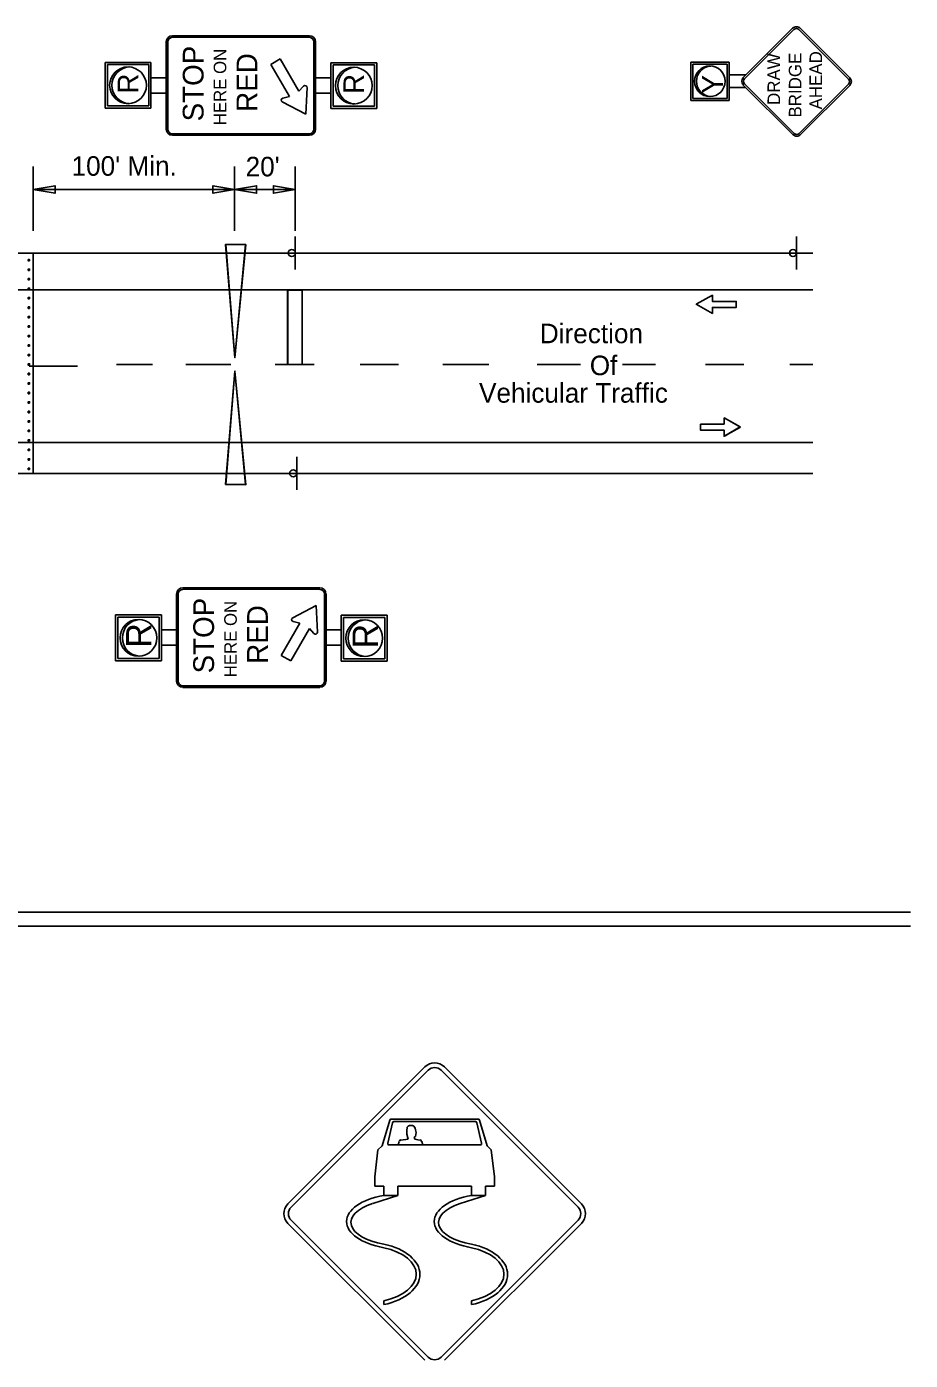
# Model space of a CAD drawing. Extents: x 15 to 764, y 7 to 487.
# Drawn here: x 605.9 to 764.1, y 233.7 to 472.6 of the extents above; entities that cross this region are included whole.
import ezdxf

# ---------------------------------------------------------------- set-up
doc = ezdxf.new("R2010")
doc.units = 0
for name, color, linetype in [('Default', 7, 'Continuous'), ('Dimension', 7, 'Continuous'), ('TextStructures', 7, 'Continuous')]:
    doc.layers.add(name, color=color, linetype=linetype)

msp = doc.modelspace()

# ---------------------------------------------------------------- linework, layer by layer
at = {"layer": 'Default'}
for p, q in [((656.48, 470.93), (631.96, 470.93)), ((656.48, 470.65), (631.96, 470.65)), ((743, 472.27), (734.18, 463.45)), ((743.23, 472.04), (734.41, 463.23)), ((753.01, 463.16), (744.13, 472.04)), ((753.24, 463.38), (744.36, 472.27)), ((630.84, 469.81), (630.84, 454.21)), ((631.12, 469.81), (631.12, 454.21)), ((657.31, 454.21), (657.31, 469.81)), ((657.59, 454.21), (657.59, 469.81)), ((628.13, 466.16), (619.91, 466.16)), ((619.91, 466.16), (619.91, 457.94)), ((628.13, 457.94), (628.13, 466.16)), ((651.26, 466.77), (649.58, 465.8)), ((654.6, 461), (651.26, 466.77)), ((668.55, 466.1), (660.33, 466.1)), ((660.33, 466.1), (660.33, 457.88)), ((668.55, 457.88), (668.55, 466.1)), ((731.62, 466.19), (724.76, 466.19)), ((724.76, 466.19), (724.76, 459.34)), ((731.27, 465.85), (725.11, 465.85)), ((725.11, 465.85), (725.11, 459.69)), ((731.27, 459.69), (731.27, 465.85)), ((731.62, 459.34), (731.62, 466.19)), ((627.72, 465.75), (620.32, 465.75)), ((620.32, 465.75), (620.32, 458.35)), ((627.72, 458.35), (627.72, 465.75)), ((649.58, 465.8), (652.91, 460.02)), ((668.14, 465.69), (660.74, 465.69)), ((660.74, 465.69), (660.74, 458.29)), ((668.14, 458.29), (668.14, 465.69)), ((731.64, 463.9), (734.63, 463.9)), ((628.12, 463.37), (630.84, 463.37)), ((655.44, 461.89), (654.6, 461)), ((655.85, 456.87), (656.07, 461.63)), ((657.59, 463.37), (660.31, 463.37)), ((731.64, 461.64), (734.64, 461.64)), ((743.06, 453.21), (734.18, 462.1)), ((743.29, 453.44), (734.41, 462.33)), ((740.2, 461.17), (740.2, 461.18)), ((753.01, 462.26), (744.19, 453.44)), ((753.24, 462.03), (744.42, 453.21)), ((628.12, 460.65), (630.84, 460.65)), ((651.63, 459.06), (655.85, 456.87)), ((652.91, 460.02), (651.72, 459.74)), ((657.59, 460.65), (660.31, 460.65)), ((724.76, 459.34), (731.62, 459.34)), ((725.11, 459.69), (731.27, 459.69)), ((619.91, 457.94), (628.13, 457.94)), ((620.32, 458.35), (627.72, 458.35)), ((660.33, 457.88), (668.55, 457.88)), ((660.74, 458.29), (668.14, 458.29)), ((631.96, 453.37), (656.48, 453.37)), ((631.96, 453.09), (656.48, 453.09)), ((607.05, 436.01), (607.05, 447.48)), ((643.11, 436.01), (643.11, 447.48)), ((653.97, 436.01), (653.97, 447.48)), ((607.05, 443.39), (643.11, 443.39)), ((643.11, 443.39), (653.97, 443.39)), ((653.97, 429.04), (653.97, 434.99)), ((743.71, 429.04), (743.71, 434.99)), ((645.08, 433.54), (641.47, 433.54)), ((641.47, 433.54), (643.15, 413.21)), ((645.08, 433.54), (641.52, 433.54)), ((643.15, 413.21), (645.08, 433.54)), ((643.16, 413.27), (645.08, 433.54)), ((401.85, 431.97), (746.65, 431.97)), ((607.05, 431.97), (539.34, 431.97)), ((607.05, 392.5), (607.05, 431.97)), ((607.05, 431.97), (641.6, 431.97)), ((401.85, 425.41), (746.65, 425.41)), ((728.65, 424.44), (725.74, 422.82)), ((728.65, 423.35), (728.65, 424.44)), ((728.65, 423.35), (728.65, 424.01)), ((732.91, 423.35), (728.65, 423.35)), ((731.99, 423.35), (728.65, 423.35)), ((732.91, 422.26), (732.91, 423.35)), ((725.74, 422.82), (728.64, 421.17)), ((728.64, 421.17), (728.64, 422.26)), ((728.64, 422.26), (732.91, 422.26)), ((728.64, 421.17), (728.64, 422.26)), ((728.64, 422.26), (728.66, 422.26)), ((728.64, 421.18), (728.64, 421.17)), ((606.33, 411.74), (614.98, 411.74)), ((621.96, 412.04), (628.41, 412.04)), ((634.39, 412.04), (642.45, 412.04)), ((650.35, 412.04), (657.35, 412.04)), ((652.62, 412.04), (655.21, 412.04)), ((665.59, 412.04), (672.45, 412.04)), ((680.37, 412.04), (688.63, 412.04)), ((697.28, 412.04), (705, 412.04)), ((712.54, 412.04), (718.47, 412.04)), ((727.39, 412.04), (734.27, 412.04)), ((742.51, 412.04), (746.65, 412.04)), ((641.47, 390.53), (643.15, 410.86)), ((643.15, 410.86), (645.08, 390.53)), ((645.08, 390.53), (643.15, 410.86)), ((730.74, 401.38), (726.49, 401.37)), ((730.74, 401.38), (726.49, 401.37)), ((726.49, 401.37), (726.49, 400.28)), ((730.75, 402.47), (730.74, 401.38)), ((730.75, 402.47), (730.74, 401.38)), ((733.65, 400.82), (730.75, 402.47)), ((733.61, 400.85), (730.75, 402.47)), ((726.49, 400.28), (730.74, 400.28)), ((730.74, 399.2), (733.65, 400.82)), ((730.74, 400.28), (730.74, 399.2)), ((730.74, 399.2), (730.9, 399.29)), ((401.85, 398.09), (746.65, 398.09)), ((654.24, 389.57), (654.24, 395.51)), ((401.85, 392.5), (746.65, 392.5)), ((539.34, 392.5), (607.05, 392.5)), ((645.08, 390.53), (641.47, 390.53)), ((641.51, 390.53), (645.08, 390.53)), ((632.72, 370.93), (632.72, 355.33)), ((633, 370.93), (633, 355.33)), ((658.35, 372.05), (633.83, 372.05)), ((658.35, 371.77), (633.83, 371.77)), ((659.19, 355.33), (659.19, 370.93)), ((659.47, 355.33), (659.47, 370.93)), ((653.51, 366.68), (657.73, 368.87)), ((657.73, 368.87), (657.95, 364.11)), ((629.99, 367.18), (621.77, 367.18)), ((621.77, 367.18), (621.77, 358.96)), ((629.58, 366.77), (622.18, 366.77)), ((622.18, 366.77), (622.18, 359.37)), ((629.58, 359.37), (629.58, 366.77)), ((629.99, 358.96), (629.99, 367.18)), ((651.45, 359.94), (654.79, 365.72)), ((654.79, 365.72), (653.59, 366)), ((670.42, 367.13), (662.2, 367.13)), ((662.2, 367.13), (662.2, 358.91)), ((670.01, 366.72), (662.61, 366.72)), ((662.61, 366.72), (662.61, 359.32)), ((670.01, 359.32), (670.01, 366.72)), ((670.42, 358.91), (670.42, 367.13)), ((630, 364.49), (632.72, 364.49)), ((656.48, 364.74), (653.14, 358.97)), ((657.31, 363.85), (656.48, 364.74)), ((659.47, 364.49), (662.19, 364.49)), ((630, 361.77), (632.72, 361.77)), ((659.47, 361.77), (662.19, 361.77)), ((621.77, 358.96), (629.99, 358.96)), ((622.18, 359.37), (629.58, 359.37)), ((653.14, 358.97), (651.45, 359.94)), ((662.2, 358.91), (670.42, 358.91)), ((662.61, 359.32), (670.01, 359.32)), ((633.83, 354.49), (658.35, 354.49)), ((633.83, 354.21), (658.35, 354.21)), ((677.16, 286.21), (652.64, 261.69)), ((677.75, 285.63), (653.23, 261.11)), ((704.6, 261.11), (680.08, 285.63)), ((705.19, 261.69), (680.67, 286.21)), ((669.5, 272.09), (670.9, 276.71)), ((671.38, 276.23), (670.51, 272.55)), ((671.14, 276.89), (686.69, 276.89)), ((686.2, 276.42), (671.63, 276.42)), ((673.92, 274.8), (674, 275.43)), ((673.92, 274.16), (673.92, 274.8)), ((674, 275.43), (674.16, 275.59)), ((675.19, 275.59), (675.43, 275.27)), ((675.43, 275.27), (675.5, 274.95)), ((675.5, 274.95), (675.58, 274.48)), ((687.32, 272.55), (686.44, 276.23)), ((686.93, 276.71), (688.33, 272.09)), ((672.41, 272.26), (672.57, 272.89)), ((672.89, 273.13), (674.16, 273.29)), ((674.16, 273.29), (673.92, 274.16)), ((675.35, 273.77), (675.27, 273.61)), ((675.27, 273.61), (675.35, 273.29)), ((675.5, 273.77), (675.35, 273.77)), ((675.35, 273.29), (676.22, 273.13)), ((675.58, 274.48), (675.5, 273.77)), ((676.61, 272.89), (676.77, 272.26)), ((668.18, 266.51), (668.77, 271.36)), ((668.77, 271.36), (669.5, 272.09)), ((670.75, 272.24), (687.08, 272.24)), ((676.78, 272.24), (672.45, 272.24)), ((688.33, 272.09), (689.06, 271.36)), ((689.06, 271.36), (689.65, 266.51)), ((668.18, 264.86), (668.18, 266.51)), ((689.65, 266.51), (689.65, 264.86)), ((672.31, 263.21), (667.82, 261.73)), ((669.83, 264.86), (668.18, 264.86)), ((669.83, 263.21), (669.83, 264.86)), ((669.83, 263.21), (672.31, 263.21)), ((672.31, 263.21), (669.83, 263.21)), ((685.52, 264.86), (672.31, 264.86)), ((672.31, 264.86), (672.31, 263.21)), ((688, 263.21), (683.5, 261.73)), ((685.52, 263.21), (685.52, 264.86)), ((685.52, 263.21), (688, 263.21)), ((688, 263.21), (685.52, 263.21)), ((689.65, 264.86), (688, 264.86)), ((688, 264.86), (688, 263.21)), ((652.64, 258.19), (677.16, 233.67)), ((653.23, 258.77), (677.75, 234.25)), ((680.08, 234.25), (704.6, 258.77)), ((680.67, 233.67), (705.19, 258.19)), ((669.83, 243.65), (669.83, 244.35)), ((685.52, 243.65), (685.52, 244.35))]:
    msp.add_line(p, q, dxfattribs=at)
for points in [[(645.11, 433.56), (641.52, 433.56), (643.16, 413.27)], [(652.59, 425.41), (652.59, 412.04), (655.22, 412.04), (655.22, 425.41)], [(655.18, 425.41), (652.62, 425.41), (652.62, 412.03), (655.21, 412.03)], [(728.64, 424.44), (725.75, 422.82), (728.64, 421.18), (728.66, 422.26), (732.91, 422.27), (732.9, 423.35), (728.66, 423.35)], [(641.51, 390.53), (645.12, 390.49), (643.15, 410.86)], [(726.49, 401.37), (730.74, 401.39), (730.75, 402.47), (733.61, 400.85), (730.88, 399.28), (730.73, 399.2), (730.73, 400.28), (726.49, 400.29)]]:
    msp.add_lwpolyline(points, close=True, dxfattribs=at)
for points in [[(641.52, 433.54), (643.16, 413.27)], [(606.4, 430.58), (606.4, 430.84), (606.14, 430.84), (606.14, 430.58), (606.4, 430.58)], [(606.4, 430.58), (606.4, 430.84), (606.14, 430.84), (606.14, 430.58), (606.4, 430.58)], [(606.4, 428.89), (606.4, 429.14), (606.14, 429.14), (606.14, 428.89), (606.4, 428.89)], [(606.4, 428.89), (606.4, 429.14), (606.14, 429.14), (606.14, 428.89), (606.4, 428.89)], [(606.4, 427.19), (606.4, 427.44), (606.14, 427.44), (606.14, 427.19), (606.4, 427.19)], [(606.4, 427.19), (606.4, 427.44), (606.14, 427.44), (606.14, 427.19), (606.4, 427.19)], [(606.4, 425.49), (606.4, 425.74), (606.14, 425.74), (606.14, 425.49), (606.4, 425.49)], [(606.4, 425.49), (606.4, 425.74), (606.14, 425.74), (606.14, 425.49), (606.4, 425.49)], [(652.59, 425.38), (655.22, 425.38)], [(655.18, 425.38), (652.62, 425.38)], [(652.62, 425.38), (652.62, 412.04)], [(655.21, 412.04), (655.18, 425.38)], [(606.4, 423.79), (606.4, 424.05), (606.14, 424.05), (606.14, 423.79), (606.4, 423.79)], [(606.4, 423.79), (606.4, 424.05), (606.14, 424.05), (606.14, 423.79), (606.4, 423.79)], [(728.65, 424.01), (728.64, 424.44), (725.75, 422.82), (728.64, 421.18)], [(728.66, 422.26), (732.91, 422.27), (732.9, 423.35), (731.99, 423.35)], [(606.4, 422.09), (606.4, 422.35), (606.14, 422.35), (606.14, 422.09), (606.4, 422.09)], [(606.4, 422.09), (606.4, 422.35), (606.14, 422.35), (606.14, 422.09), (606.4, 422.09)], [(606.4, 420.39), (606.4, 420.65), (606.14, 420.65), (606.14, 420.39), (606.4, 420.39)], [(606.4, 420.39), (606.4, 420.65), (606.14, 420.65), (606.14, 420.39), (606.4, 420.39)], [(606.4, 418.7), (606.4, 418.95), (606.14, 418.95), (606.14, 418.7), (606.4, 418.7)], [(606.4, 418.7), (606.4, 418.95), (606.14, 418.95), (606.14, 418.7), (606.4, 418.7)], [(606.4, 417), (606.4, 417.25), (606.14, 417.25), (606.14, 417), (606.4, 417)], [(606.4, 417), (606.4, 417.25), (606.14, 417.25), (606.14, 417), (606.4, 417)], [(606.4, 415.3), (606.4, 415.55), (606.14, 415.55), (606.14, 415.3), (606.4, 415.3)], [(606.4, 415.3), (606.4, 415.55), (606.14, 415.55), (606.14, 415.3), (606.4, 415.3)], [(606.4, 413.6), (606.4, 413.86), (606.14, 413.85), (606.14, 413.6), (606.4, 413.6)], [(606.4, 413.6), (606.4, 413.86), (606.14, 413.85), (606.14, 413.6), (606.4, 413.6)], [(606.4, 411.9), (606.4, 412.16), (606.14, 412.16), (606.14, 411.9), (606.4, 411.9)], [(606.4, 411.9), (606.4, 412.16), (606.14, 412.16), (606.14, 411.9), (606.4, 411.9)], [(606.4, 410.2), (606.4, 410.46), (606.14, 410.46), (606.14, 410.2), (606.4, 410.2)], [(606.4, 410.2), (606.4, 410.46), (606.14, 410.46), (606.14, 410.2), (606.4, 410.2)], [(606.4, 408.5), (606.4, 408.76), (606.14, 408.76), (606.14, 408.5), (606.4, 408.5)], [(606.4, 408.5), (606.4, 408.76), (606.14, 408.76), (606.14, 408.5), (606.4, 408.5)], [(643.15, 410.86), (641.51, 390.53)], [(606.4, 406.81), (606.4, 407.06), (606.14, 407.06), (606.14, 406.81), (606.4, 406.81)], [(606.4, 406.81), (606.4, 407.06), (606.14, 407.06), (606.14, 406.81), (606.4, 406.81)], [(606.4, 405.11), (606.4, 405.36), (606.14, 405.36), (606.14, 405.11), (606.4, 405.11)], [(606.4, 405.11), (606.4, 405.36), (606.14, 405.36), (606.14, 405.11), (606.4, 405.11)], [(606.4, 403.41), (606.4, 403.66), (606.14, 403.66), (606.14, 403.41), (606.4, 403.41)], [(606.4, 403.41), (606.4, 403.66), (606.14, 403.66), (606.14, 403.41), (606.4, 403.41)], [(606.4, 401.71), (606.4, 401.97), (606.14, 401.97), (606.14, 401.71), (606.4, 401.71)], [(606.4, 401.71), (606.4, 401.97), (606.14, 401.97), (606.14, 401.71), (606.4, 401.71)], [(726.49, 401.37), (726.49, 400.29), (730.73, 400.28)], [(606.4, 400.01), (606.4, 400.27), (606.14, 400.27), (606.14, 400.01), (606.4, 400.01)], [(606.4, 400.01), (606.4, 400.27), (606.14, 400.27), (606.14, 400.01), (606.4, 400.01)], [(730.73, 400.28), (730.73, 399.2)], [(730.9, 399.29), (733.61, 400.85)], [(606.4, 398.31), (606.4, 398.57), (606.14, 398.57), (606.14, 398.31), (606.4, 398.31)], [(606.4, 398.31), (606.4, 398.57), (606.14, 398.57), (606.14, 398.31), (606.4, 398.31)], [(606.4, 396.61), (606.4, 396.87), (606.14, 396.87), (606.14, 396.61), (606.4, 396.61)], [(606.4, 396.61), (606.4, 396.87), (606.14, 396.87), (606.14, 396.61), (606.4, 396.61)], [(606.4, 394.92), (606.4, 395.17), (606.14, 395.17), (606.14, 394.92), (606.4, 394.92)], [(606.4, 394.92), (606.4, 395.17), (606.14, 395.17), (606.14, 394.92), (606.4, 394.92)], [(606.4, 393.22), (606.4, 393.47), (606.14, 393.47), (606.14, 393.22), (606.4, 393.22)], [(606.4, 393.22), (606.4, 393.47), (606.14, 393.47), (606.14, 393.22), (606.4, 393.22)]]:
    msp.add_lwpolyline(points, dxfattribs=at)
for centre, radius in [((624.02, 462.05), 3.29), ((664.44, 461.99), 3.29), ((728.19, 462.77), 2.74), ((653.33, 432.02), 0.637), ((743.07, 432.01), 0.637), ((653.6, 392.54), 0.637), ((625.88, 363.07), 3.29), ((666.31, 363.02), 3.29)]:
    msp.add_circle(centre, radius, dxfattribs=at)
for centre, radius, start, end in [((631.96, 469.81), 1.11, 90, 180), ((631.96, 469.81), 0.836, 90, 180), ((656.48, 469.81), 1.11, 360, 90), ((656.48, 469.81), 0.836, 360, 90), ((743.68, 471.59), 0.958, 44.9848, 134.9852), ((743.68, 471.59), 0.635, 44.9848, 134.9852), ((624.43, 462.05), 3.29, 93.5833, 266.4167), ((664.85, 461.99), 3.29, 93.5833, 266.4167), ((728.53, 462.77), 2.74, 93.5833, 266.4167), ((734.86, 462.78), 0.958, 134.9852, 224.9843), ((655.7, 461.64), 0.366, 357.4033, 136.9437), ((734.86, 462.78), 0.635, 134.9852, 224.9843), ((752.56, 462.71), 0.635, 314.9857, 44.9846), ((752.56, 462.71), 0.958, 314.9857, 44.9846), ((651.8, 459.39), 0.366, 103.0563, 242.5967), ((631.96, 454.21), 1.11, 180, 270), ((631.96, 454.21), 0.836, 180, 270), ((656.48, 454.21), 1.11, 270, 360), ((656.48, 454.21), 0.836, 270, 360), ((743.74, 453.89), 0.958, 224.9847, 314.9857), ((743.74, 453.89), 0.635, 224.9847, 314.9857), ((633.83, 370.93), 1.11, 90, 180), ((633.83, 370.93), 0.836, 90, 180), ((658.35, 370.93), 1.11, 360, 90), ((658.35, 370.93), 0.836, 360, 90), ((626.29, 363.07), 3.29, 93.5833, 266.4167), ((653.67, 366.35), 0.366, 117.4033, 256.9437), ((666.72, 363.02), 3.29, 93.5833, 266.4167), ((657.58, 364.1), 0.366, 223.0563, 2.5967), ((633.83, 355.33), 1.11, 180, 270), ((633.83, 355.33), 0.836, 180, 270), ((658.35, 355.33), 1.11, 270, 360), ((658.35, 355.33), 0.836, 270, 360), ((678.91, 284.46), 2.48, 45, 135), ((678.91, 284.46), 1.65, 45, 135), ((671.14, 276.64), 0.248, 90, 163.133), ((671.63, 276.17), 0.248, 90, 166.6434), ((674.67, 274.65), 1.1, 61.5674, 118.4326), ((686.2, 276.17), 0.248, 13.3566, 90), ((686.69, 276.64), 0.248, 16.8669, 90), ((670.75, 272.49), 0.248, 166.6434, 270), ((672.89, 272.85), 0.303, 96.2729, 166.6932), ((676.21, 272.78), 0.392, 16.03, 82.8338), ((687.08, 272.49), 0.248, 270, 13.3566), ((654.39, 259.94), 2.48, 135, 225), ((654.39, 259.94), 1.65, 135, 225), ((703.43, 259.94), 1.65, 315, 45), ((703.43, 259.94), 2.48, 315, 45), ((678.91, 235.42), 1.65, 225, 315)]:
    msp.add_arc(centre, radius, start, end, dxfattribs=at)
for centre, major_axis, ratio, start_param, end_param in [((673.06, 258.53), (9.91, 0), 0.5, 1.902923, 4.380262), ((688.75, 258.53), (9.91, 0), 0.5, 1.902923, 4.380262), ((673.01, 258.35), (9.08, 0), 0.454545, 2.180257, 4.354407), ((688.7, 258.35), (9.08, 0), 0.454545, 2.180257, 4.354407), ((666.38, 249.06), (9.91, 0), 0.583333, 5.068422, 7.497948), ((666.38, 249.09), (9.25, 0), 0.553572, 5.095121, 7.47125), ((682.07, 249.06), (9.91, 0), 0.583333, 5.068422, 7.497948), ((682.07, 249.09), (9.25, 0), 0.553572, 5.095121, 7.47125)]:
    msp.add_ellipse(centre, major_axis=major_axis, ratio=ratio, start_param=start_param, end_param=end_param, dxfattribs=at)
at = {"layer": 'Dimension'}
for points in [[(607.05, 443.39), (610.96, 442.72), (610.96, 444.05)], [(643.11, 443.39), (639.21, 444.05), (639.21, 442.72)], [(643.11, 443.39), (647.02, 442.72), (647.02, 444.05)], [(653.97, 443.39), (650.06, 444.05), (650.06, 442.72)]]:
    msp.add_lwpolyline(points, close=True, dxfattribs=at)
at = {"layer": 'TextStructures'}
for p, q in [((446.19, 313.96), (764.08, 313.96)), ((446.19, 311.46), (764.08, 311.46))]:
    msp.add_line(p, q, dxfattribs=at)

# ---------------------------------------------------------------- texts
at = {"layer": 'Default'}
for s, height, p in [('STOP', 3.718, (637.54, 455.59)), ('HERE ON', 2.247, (641.61, 454.9)), ('RED', 3.718, (647.17, 457.3)), ('DRAW', 2.265, (740.77, 458.53)), ('BRIDGE', 2.265, (744.59, 456.28)), ('AHEAD', 2.265, (748.29, 457.72)), ('STOP', 3.718, (639.42, 356.71)), ('HERE ON', 2.247, (643.49, 356.02)), ('RED', 3.718, (649.05, 358.43))]:
    msp.add_text(s, height=height, rotation=90, dxfattribs=at).set_placement(p)
at = {"layer": 'TextStructures'}
for s, height, rotation, p in [('R', 3.7, 90, (625.87, 460.57)), ('R', 3.7, 90, (666.29, 460.51)), ('Y', 3.78, 90, (730.55, 460.54)), ("100' Min.", 3.5, 0.0007, (613.91, 445.85)), ("20'", 3.5, 0.0007, (645.07, 445.74)), ('R', 4.54, 90, (628.21, 361.32)), ('R', 4.54, 90, (668.77, 361.2))]:
    msp.add_text(s, height=height, rotation=rotation, dxfattribs=at).set_placement(p)
for s, p in [('Direction', (697.75, 415.85)), ('Of', (706.69, 410.13)), ('Vehicular Traffic', (686.86, 405.2))]:
    msp.add_text(s, height=3.5, dxfattribs=at).set_placement(p)

doc.saveas('drawing.dxf')
